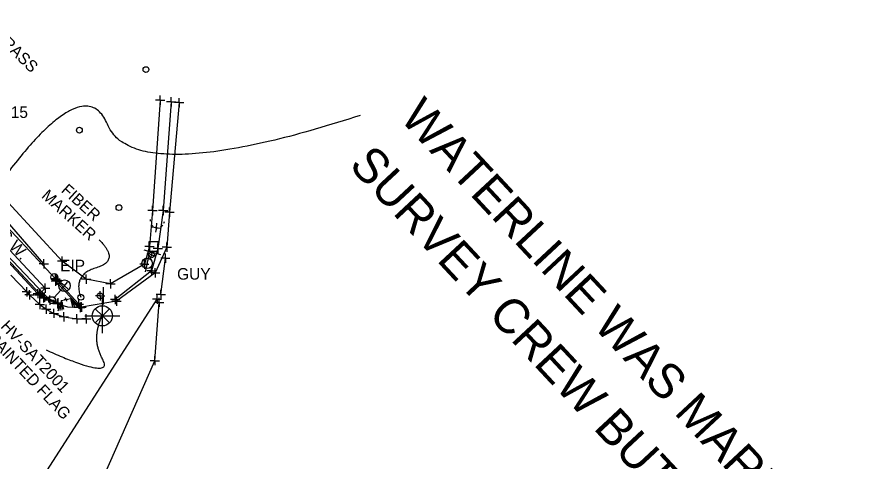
# Model space of a CAD drawing. Extents: x 0 to 1944463, y 0 to 420651.
# Drawn here: x 1943722 to 1944092.5, y 416896 to 417088.1 of the extents above; entities that cross this region are included whole.
import ezdxf

# ---------------------------------------------------------------- set-up
doc = ezdxf.new("R2010")
doc.units = 0
for name, color, linetype in [('AERIAL - CTRL - Points', 7, 'Continuous'), ('AERIAL - CTRL - Text', 7, 'Continuous'), ('SUR - CTRL - Points Text', 7, 'Continuous'), ('SUR - DTM - Breaklines', 7, 'Continuous'), ('SUR - DTM - Breaklines - Points - Locators', 7, 'Continuous'), ('SUR - DTM - Spot Points - Locators', 7, 'Continuous'), ('SUR - PROPERTY - Property Lines', 7, 'Continuous'), ('SUR - PROPERTY - Property Markers', 7, 'Continuous'), ('SUR - TR-CTRL - Signs and Devices', 7, 'Continuous'), ('SUR - TR-CTRL - Signs and Devices - Points - Locators', 7, 'Continuous'), ('SUR - TRAN - Features', 7, 'Continuous'), ('SUR - TRAN - Features - Points - Locators', 7, 'Continuous'), ('SUR - TRAN - Features Text', 7, 'Continuous'), ('SUR - TRAN - Roads', 7, 'Continuous'), ('SUR - UTL - Electric (Lighting)', 7, 'Continuous'), ('SUR - UTL - Electric (Lighting) - Points - Locators', 7, 'Continuous'), ('SUR - UTL - Fiber Optic Cable (Underground) Text', 7, 'Continuous'), ('SUR - UTL - Gas', 7, 'Continuous'), ('SUR - UTL - Gas - Points - Locators', 7, 'Continuous'), ('SUR - UTL - Poles and Miscellaneous', 7, 'Continuous'), ('SUR - UTL - Poles and Miscellaneous - Points - Locators', 7, 'Continuous'), ('SUR - UTL - Poles and Miscellaneous Text', 7, 'Continuous'), ('SUR - UTL - Water', 7, 'Continuous'), ('SUR - UTL - Water - Points - Locators', 7, 'Continuous'), ('SUR - UTL - Water Text', 7, 'Continuous'), ('SUR - VEG - Features Text', 7, 'Continuous')]:
    doc.layers.add(name, color=color, linetype=linetype)

msp = doc.modelspace()

# ---------------------------------------------------------------- linework, layer by layer
at = {"layer": 'AERIAL - CTRL - Points'}
for p, q in [((1943758.84, 416959.12), (1943758.84, 416966.62)), ((1943758.84, 416959.12), (1943755.78, 416962.19)), ((1943758.84, 416959.12), (1943761.91, 416962.19)), ((1943751.34, 416959.12), (1943758.84, 416959.12)), ((1943755.76, 416956.04), (1943758.84, 416959.12)), ((1943758.84, 416959.12), (1943758.84, 416959.12)), ((1943758.84, 416959.12), (1943766.34, 416959.12)), ((1943761.93, 416956.04), (1943758.84, 416959.12)), ((1943758.84, 416951.62), (1943758.84, 416959.12))]:
    msp.add_line(p, q, dxfattribs=at)
msp.add_circle((1943758.84, 416959.11), 4.35, dxfattribs=at)
at = {"layer": 'AERIAL - CTRL - Text'}
msp.add_open_spline([(1943734.51, 416944.38), (1943764.06, 416931.1), (1943753.96, 416949.44), (1943758.84, 416959.12)], degree=2, dxfattribs=at)
at = {"layer": 'SUR - DTM - Breaklines'}
for points in [[(1943783.81, 417052.2), (1943780.54, 417004.6), (1943779.21, 416989.03), (1943776.98, 416981.36), (1943762.37, 416972.89), (1943751.86, 416974.9), (1943741.51, 416982.77), (1943718.16, 417008.08), (1943685.34, 417042.9), (1943654.02, 417077.16), (1943664.76, 417124.78), (1943668.66, 417143.41)], [(1943733.58, 416981.53), (1943714.06, 417003.91), (1943681.39, 417038.59), (1943646.39, 417076.86)], [(1943792.05, 417051.17), (1943787.81, 417003.83), (1943786.74, 416988.77), (1943781.64, 416977.66), (1943764.93, 416965.46), (1943749.88, 416962.89)], [(1943788.57, 417051.56), (1943785.14, 417004.61), (1943782.85, 416988.15), (1943780.09, 416978.59), (1943764.41, 416966.11)], [(1943739.71, 416964.71), (1943733.87, 416967.21), (1943731.83, 416968.57), (1943702.93, 416999.44), (1943684.69, 417018.93), (1943683.82, 417020.85), (1943684.01, 417022.49), (1943684.83, 417023.71)], [(1943749.72, 416962.96), (1943748.68, 416964.11), (1943739.24, 416974.49)]]:
    msp.add_lwpolyline(points, dxfattribs=at)
at = {"layer": 'SUR - DTM - Breaklines - Points - Locators'}
for p, q in [((1943783.81, 417052.2), (1943783.81, 417054.2)), ((1943788.57, 417051.56), (1943788.57, 417053.56)), ((1943783.81, 417052.2), (1943781.81, 417052.2)), ((1943783.81, 417052.2), (1943785.81, 417052.2)), ((1943783.81, 417052.2), (1943783.81, 417050.2)), ((1943788.57, 417051.56), (1943786.57, 417051.56)), ((1943788.57, 417051.56), (1943790.57, 417051.56)), ((1943788.57, 417051.56), (1943788.57, 417049.56)), ((1943792.05, 417051.17), (1943790.05, 417051.17)), ((1943792.05, 417051.17), (1943792.05, 417053.17)), ((1943792.05, 417051.17), (1943794.05, 417051.17)), ((1943792.05, 417051.17), (1943792.05, 417049.17)), ((1943780.54, 417004.6), (1943780.54, 417006.6)), ((1943785.14, 417004.61), (1943785.14, 417006.61)), ((1943787.81, 417003.83), (1943787.81, 417005.83)), ((1943780.54, 417004.6), (1943778.54, 417004.6)), ((1943780.54, 417004.6), (1943782.54, 417004.6)), ((1943780.54, 417004.6), (1943780.54, 417002.6)), ((1943785.14, 417004.61), (1943783.14, 417004.61)), ((1943785.14, 417004.61), (1943787.14, 417004.61)), ((1943785.14, 417004.61), (1943785.14, 417002.61)), ((1943787.81, 417003.83), (1943785.81, 417003.83)), ((1943787.81, 417003.83), (1943789.81, 417003.83)), ((1943787.81, 417003.83), (1943787.81, 417001.83)), ((1943779.21, 416989.03), (1943779.21, 416991.03)), ((1943786.74, 416988.77), (1943786.74, 416990.77)), ((1943779.21, 416989.03), (1943777.21, 416989.03)), ((1943779.21, 416989.03), (1943781.21, 416989.03)), ((1943779.21, 416989.03), (1943779.21, 416987.03)), ((1943782.85, 416988.15), (1943780.85, 416988.15)), ((1943782.85, 416988.15), (1943782.85, 416990.15)), ((1943782.85, 416988.15), (1943784.85, 416988.15)), ((1943782.85, 416988.15), (1943782.85, 416986.15)), ((1943786.74, 416988.77), (1943784.74, 416988.77)), ((1943786.74, 416988.77), (1943788.74, 416988.77)), ((1943786.74, 416988.77), (1943786.74, 416986.77)), ((1943733.58, 416981.53), (1943733.58, 416983.53)), ((1943741.51, 416982.77), (1943741.51, 416984.77)), ((1943776.98, 416981.36), (1943776.98, 416983.36)), ((1943733.58, 416981.53), (1943731.58, 416981.53)), ((1943733.58, 416981.53), (1943735.58, 416981.53)), ((1943733.58, 416981.53), (1943733.58, 416979.53)), ((1943741.51, 416982.77), (1943739.51, 416982.77)), ((1943741.51, 416982.77), (1943743.51, 416982.77)), ((1943741.51, 416982.77), (1943741.51, 416980.77)), ((1943776.98, 416981.36), (1943774.98, 416981.36)), ((1943776.98, 416981.36), (1943778.98, 416981.36)), ((1943776.98, 416981.36), (1943776.98, 416979.36)), ((1943780.09, 416978.59), (1943780.09, 416980.59)), ((1943781.64, 416977.66), (1943781.64, 416979.66)), ((1943739.24, 416974.49), (1943739.24, 416976.49)), ((1943751.86, 416974.9), (1943751.86, 416976.9)), ((1943780.09, 416978.59), (1943778.09, 416978.59)), ((1943781.64, 416977.66), (1943779.64, 416977.66)), ((1943780.09, 416978.59), (1943782.09, 416978.59)), ((1943780.09, 416978.59), (1943780.09, 416976.59)), ((1943781.64, 416977.66), (1943783.64, 416977.66)), ((1943781.64, 416977.66), (1943781.64, 416975.66)), ((1943739.24, 416974.49), (1943737.24, 416974.49)), ((1943739.24, 416974.49), (1943741.24, 416974.49)), ((1943739.24, 416974.49), (1943739.24, 416972.49)), ((1943751.86, 416974.9), (1943749.86, 416974.9)), ((1943751.86, 416974.9), (1943753.86, 416974.9)), ((1943751.86, 416974.9), (1943751.86, 416972.9)), ((1943762.37, 416972.89), (1943760.37, 416972.89)), ((1943762.37, 416972.89), (1943762.37, 416974.89)), ((1943762.37, 416972.89), (1943764.37, 416972.89)), ((1943762.37, 416972.89), (1943762.37, 416970.89)), ((1943731.83, 416968.57), (1943729.83, 416968.57)), ((1943731.83, 416968.57), (1943731.83, 416970.57)), ((1943731.83, 416968.57), (1943733.83, 416968.57)), ((1943731.83, 416968.57), (1943731.83, 416966.57)), ((1943733.87, 416967.21), (1943733.87, 416969.21)), ((1943733.87, 416967.21), (1943731.87, 416967.21)), ((1943733.87, 416967.21), (1943735.87, 416967.21)), ((1943733.87, 416967.21), (1943733.87, 416965.21)), ((1943739.71, 416964.71), (1943737.71, 416964.71)), ((1943739.71, 416964.71), (1943739.71, 416966.71)), ((1943739.71, 416964.71), (1943741.71, 416964.71)), ((1943739.71, 416964.71), (1943739.71, 416962.71)), ((1943748.68, 416964.11), (1943748.68, 416966.11)), ((1943749.72, 416962.96), (1943749.72, 416964.96)), ((1943749.88, 416962.89), (1943749.88, 416964.89)), ((1943764.41, 416966.11), (1943762.41, 416966.11)), ((1943764.93, 416965.46), (1943762.93, 416965.46)), ((1943764.41, 416966.11), (1943764.41, 416968.11)), ((1943764.41, 416966.11), (1943766.41, 416966.11)), ((1943764.41, 416966.11), (1943764.41, 416964.11)), ((1943764.93, 416965.46), (1943764.93, 416967.46)), ((1943764.93, 416965.46), (1943766.93, 416965.46)), ((1943764.93, 416965.46), (1943764.93, 416963.46)), ((1943748.68, 416964.11), (1943746.68, 416964.11)), ((1943749.72, 416962.96), (1943747.72, 416962.96)), ((1943749.88, 416962.89), (1943747.88, 416962.89)), ((1943748.68, 416964.11), (1943750.68, 416964.11)), ((1943748.68, 416964.11), (1943748.68, 416962.11)), ((1943749.72, 416962.96), (1943751.72, 416962.96)), ((1943749.72, 416962.96), (1943749.72, 416960.96)), ((1943749.88, 416962.89), (1943751.88, 416962.89)), ((1943749.88, 416962.89), (1943749.88, 416960.89))]:
    msp.add_line(p, q, dxfattribs=at)
at = {"layer": 'SUR - DTM - Spot Points - Locators'}
for p, q in [((1943777.69, 417065.43), (1943777.69, 417065.43)), ((1943748.91, 417039.28), (1943748.91, 417039.28)), ((1943766.02, 417005.81), (1943766.02, 417005.81))]:
    msp.add_line(p, q, dxfattribs=at)
for centre in [(1943777.68, 417065.44), (1943748.9, 417039.29), (1943766.01, 417005.82)]:
    msp.add_circle(centre, 1.25, dxfattribs=at)
at = {"layer": 'SUR - PROPERTY - Property Lines'}
for p, q in [((1943726.16, 416969.43), (1943724.16, 416969.43)), ((1943726.16, 416969.43), (1943726.16, 416971.43)), ((1943726.16, 416969.43), (1943728.16, 416969.43)), ((1943726.16, 416969.43), (1943726.16, 416967.43)), ((1943727.36, 416968.16), (1943727.36, 416970.16)), ((1943727.36, 416968.16), (1943725.36, 416968.16)), ((1943727.36, 416968.16), (1943729.36, 416968.16)), ((1943727.36, 416968.16), (1943727.36, 416966.16)), ((1943731.81, 416963.96), (1943731.81, 416965.96)), ((1943731.81, 416963.96), (1943729.81, 416963.96)), ((1943731.81, 416963.96), (1943733.81, 416963.96)), ((1943731.81, 416963.96), (1943731.81, 416961.96)), ((1943734.56, 416961.94), (1943732.56, 416961.94)), ((1943734.56, 416961.94), (1943734.56, 416963.94)), ((1943734.56, 416961.94), (1943736.56, 416961.94)), ((1943734.56, 416961.94), (1943734.56, 416959.94)), ((1943737.91, 416960.18), (1943737.91, 416962.18)), ((1943737.91, 416960.18), (1943735.91, 416960.18)), ((1943737.91, 416960.18), (1943739.91, 416960.18)), ((1943737.91, 416960.18), (1943737.91, 416958.18)), ((1943742.17, 416958.72), (1943740.17, 416958.72)), ((1943742.17, 416958.72), (1943742.17, 416960.72)), ((1943742.17, 416958.72), (1943744.17, 416958.72)), ((1943742.17, 416958.72), (1943742.17, 416956.72)), ((1943747.76, 416957.86), (1943745.76, 416957.86)), ((1943747.76, 416957.86), (1943747.76, 416959.86)), ((1943747.76, 416957.86), (1943749.76, 416957.86)), ((1943747.76, 416957.86), (1943747.76, 416955.86)), ((1943751.91, 416957.83), (1943749.91, 416957.83)), ((1943751.91, 416957.83), (1943751.91, 416959.83)), ((1943751.91, 416957.83), (1943753.91, 416957.83)), ((1943751.91, 416957.83), (1943751.91, 416955.83))]:
    msp.add_line(p, q, dxfattribs=at)
at = {"layer": 'SUR - PROPERTY - Property Markers'}
msp.add_circle((1943738.1, 416975.85), 1.5, dxfattribs=at)
at = {"layer": 'SUR - TR-CTRL - Signs and Devices'}
for p, q in [((1943776.81, 416987.66), (1943784, 416985.54)), ((1943759.13, 416971.46), (1943759.13, 416963.96))]:
    msp.add_line(p, q, dxfattribs=at)
for centre in [(1943780.07, 416985.4), (1943757.88, 416967.69)]:
    msp.add_circle(centre, 1.25, dxfattribs=at)
at = {"layer": 'SUR - TR-CTRL - Signs and Devices - Points - Locators'}
for p, q in [((1943780.06, 416985.43), (1943780.63, 416987.35)), ((1943780.06, 416985.43), (1943778.14, 416985.99)), ((1943780.06, 416985.43), (1943779.49, 416983.51)), ((1943780.06, 416985.43), (1943781.98, 416984.86)), ((1943757.9, 416967.71), (1943757.9, 416969.71)), ((1943757.9, 416967.71), (1943755.9, 416967.71)), ((1943757.9, 416967.71), (1943757.9, 416965.71)), ((1943757.9, 416967.71), (1943759.9, 416967.71))]:
    msp.add_line(p, q, dxfattribs=at)
at = {"layer": 'SUR - TRAN - Features'}
for p, q in [((1943741.23, 416965.67), (1943739.59, 416961.13)), ((1943741.23, 416965.67), (1943740.47, 416961.35)), ((1943741.23, 416965.67), (1943745.11, 416966.65)), ((1943742.21, 416961.79), (1943741.23, 416965.67)), ((1943741.23, 416965.67), (1943741.34, 416961.57)), ((1943745.11, 416966.65), (1943746.09, 416962.77)), ((1943745.11, 416966.65), (1943748.71, 416963.43)), ((1943745.11, 416966.65), (1943747.83, 416963.21)), ((1943745.11, 416966.65), (1943746.96, 416962.99))]:
    msp.add_line(p, q, dxfattribs=at)
for points in [[(1943738.63, 416975.05), (1943710.04, 417005.57), (1943644.86, 417075.55)], [(1943739.52, 416964.25), (1943733.49, 416966.8), (1943731.67, 416968.06), (1943730.97, 416968.67), (1943702.44, 416999.08), (1943684.33, 417018.55), (1943683.3, 417020.99), (1943683.5, 417022.63), (1943684.23, 417023.84)], [(1943731.91, 416968.71), (1943734.2, 416971.01), (1943705.27, 417002.05), (1943685.05, 417023.73)], [(1943749.31, 416962.68), (1943738.67, 416974.07)], [(1943739.52, 416964.25), (1943743.73, 416962.97), (1943749.31, 416962.68)]]:
    msp.add_lwpolyline(points, dxfattribs=at)
at = {"layer": 'SUR - TRAN - Features - Points - Locators'}
for p, q in [((1943738.63, 416975.05), (1943738.63, 416977.05)), ((1943738.67, 416974.07), (1943738.67, 416976.07)), ((1943734.2, 416971.01), (1943734.2, 416973.01)), ((1943738.63, 416975.05), (1943736.63, 416975.05)), ((1943738.67, 416974.07), (1943736.67, 416974.07)), ((1943738.63, 416975.05), (1943740.63, 416975.05)), ((1943738.63, 416975.05), (1943738.63, 416973.05)), ((1943738.67, 416974.07), (1943740.67, 416974.07)), ((1943738.67, 416974.07), (1943738.67, 416972.07)), ((1943730.97, 416968.67), (1943728.97, 416968.67)), ((1943731.91, 416968.71), (1943729.91, 416968.71)), ((1943730.97, 416968.67), (1943730.97, 416970.67)), ((1943730.97, 416968.67), (1943732.97, 416968.67)), ((1943730.97, 416968.67), (1943730.97, 416966.67)), ((1943731.67, 416968.06), (1943731.67, 416970.06)), ((1943731.91, 416968.71), (1943731.91, 416970.71)), ((1943731.91, 416968.71), (1943733.91, 416968.71)), ((1943731.91, 416968.71), (1943731.91, 416966.71)), ((1943734.2, 416971.01), (1943732.2, 416971.01)), ((1943733.49, 416966.8), (1943733.49, 416968.8)), ((1943734.2, 416971.01), (1943736.2, 416971.01)), ((1943734.2, 416971.01), (1943734.2, 416969.01)), ((1943731.67, 416968.06), (1943729.67, 416968.06)), ((1943733.49, 416966.8), (1943731.49, 416966.8)), ((1943731.67, 416968.06), (1943733.67, 416968.06)), ((1943731.67, 416968.06), (1943731.67, 416966.06)), ((1943733.49, 416966.8), (1943735.49, 416966.8)), ((1943733.49, 416966.8), (1943733.49, 416964.8)), ((1943739.52, 416964.25), (1943739.52, 416966.25)), ((1943743.17, 416966.16), (1943742.39, 416965.96)), ((1943743.17, 416966.16), (1943742.97, 416966.94)), ((1943743.17, 416966.16), (1943743.95, 416966.36)), ((1943743.17, 416966.16), (1943743.37, 416965.38)), ((1943749.31, 416962.68), (1943749.31, 416964.68)), ((1943739.52, 416964.25), (1943737.52, 416964.25)), ((1943739.52, 416964.25), (1943741.52, 416964.25)), ((1943739.52, 416964.25), (1943739.52, 416962.25)), ((1943749.31, 416962.68), (1943747.31, 416962.68)), ((1943749.31, 416962.68), (1943751.31, 416962.68)), ((1943749.31, 416962.68), (1943749.31, 416960.68))]:
    msp.add_line(p, q, dxfattribs=at)
at = {"layer": 'SUR - TRAN - Roads'}
msp.add_lwpolyline([(1943719.28, 416976.69), (1943726.16, 416969.43), (1943727.36, 416968.16), (1943731.81, 416963.96), (1943734.56, 416961.94), (1943737.91, 416960.18), (1943742.17, 416958.72), (1943747.76, 416957.86), (1943751.91, 416957.83)], dxfattribs=at)
at = {"layer": 'SUR - UTL - Electric (Lighting)'}
msp.add_line((1943738.06, 416967), (1943740.84, 416970.21), dxfattribs=at)
for centre, radius in [((1943742.48, 416972.1), 2.5), ((1943737.08, 416965.86), 1.5)]:
    msp.add_circle(centre, radius, dxfattribs=at)
at = {"layer": 'SUR - UTL - Electric (Lighting) - Points - Locators'}
for q in [(1943740.97, 416973.39), (1943741.18, 416970.57), (1943743.8, 416973.59), (1943744, 416970.77)]:
    msp.add_line((1943742.49, 416972.08), q, dxfattribs=at)
at = {"layer": 'SUR - UTL - Fiber Optic Cable (Underground) Text'}
msp.add_open_spline([(1943757.4, 416991.99), (1943766.62, 416982.9), (1943745.92, 416976.84), (1943749.55, 416967.1)], degree=2, dxfattribs=at)
at = {"layer": 'SUR - UTL - Gas'}
msp.add_line((1943780.95, 416989.01), (1943780.95, 416989.01), dxfattribs=at)
for points in [[(1943778.95, 416991.01), (1943778.95, 416987.01), (1943782.95, 416987.01), (1943782.95, 416991.01), (1943778.95, 416991.01)], [(1943784.08, 416968.29), (1943786.06, 416983.99)], [(1943659.63, 416706.42), (1943699.05, 416836.64), (1943782.46, 416966.29)], [(1943749.68, 416699.6), (1943706.85, 416732.94), (1943730.4, 416823.99), (1943781.49, 416939.73), (1943783.33, 416964.93)]]:
    msp.add_lwpolyline(points, dxfattribs=at)
at = {"layer": 'SUR - UTL - Gas - Points - Locators'}
for p, q in [((1943786.06, 416983.99), (1943784.06, 416983.99)), ((1943786.06, 416983.99), (1943786.06, 416985.99)), ((1943786.06, 416983.99), (1943788.06, 416983.99)), ((1943786.06, 416983.99), (1943786.06, 416981.99)), ((1943784.08, 416968.29), (1943782.08, 416968.29)), ((1943782.46, 416966.29), (1943782.46, 416968.29)), ((1943784.08, 416968.29), (1943784.08, 416970.29)), ((1943784.08, 416968.29), (1943786.08, 416968.29)), ((1943784.08, 416968.29), (1943784.08, 416966.29)), ((1943782.46, 416966.29), (1943780.46, 416966.29)), ((1943783.33, 416964.93), (1943781.33, 416964.93)), ((1943782.46, 416966.29), (1943784.46, 416966.29)), ((1943782.46, 416966.29), (1943782.46, 416964.29)), ((1943783.33, 416964.93), (1943783.33, 416966.93)), ((1943783.33, 416964.93), (1943785.33, 416964.93)), ((1943783.33, 416964.93), (1943783.33, 416962.93)), ((1943781.49, 416939.73), (1943779.49, 416939.73)), ((1943781.49, 416939.73), (1943781.49, 416941.73)), ((1943781.49, 416939.73), (1943783.49, 416939.73)), ((1943781.49, 416939.73), (1943781.49, 416937.73))]:
    msp.add_line(p, q, dxfattribs=at)
at = {"layer": 'SUR - UTL - Poles and Miscellaneous'}
for p, q in [((1943782.06, 416996.48), (1943782.16, 416997.17)), ((1943778.21, 416981.78), (1943779.15, 416985.41)), ((1943778.21, 416981.78), (1943777.28, 416978.15)), ((1943749.55, 416967.1), (1943749.55, 416967.1))]:
    msp.add_line(p, q, dxfattribs=at)
for centre, radius in [((1943778.21, 416981.78), 2.25), ((1943749.54, 416967.11), 1.25)]:
    msp.add_circle(centre, radius, dxfattribs=at)
for start, end in [(171.8731, 186.4939), (213.7509, 234.0934), (295.4358, 320.2058), (337.0596, 350.949), (249.394, 275.9093)]:
    msp.add_arc((1943782.57, 417000.27), 3.12, start, end, dxfattribs=at)
at = {"layer": 'SUR - UTL - Poles and Miscellaneous - Points - Locators'}
for q in [(1943782.44, 416999.15), (1943780.18, 416997.45), (1943781.87, 416995.19), (1943784.14, 416996.89)]:
    msp.add_line((1943782.16, 416997.17), q, dxfattribs=at)
at = {"layer": 'SUR - UTL - Water'}
msp.add_lwpolyline([(1943736.14, 416965.92), (1943698.62, 417005.31), (1943662.81, 417044.53), (1943623.49, 417086.6), (1943587.47, 417125.24), (1943551.37, 417163.71), (1943514.78, 417202.79), (1943477.5, 417242.51), (1943442.36, 417279.47), (1943414.8, 417309.89), (1943402.76, 417322.35)], dxfattribs=at)
at = {"layer": 'SUR - UTL - Water - Points - Locators'}
for q in [(1943734.14, 416965.92), (1943736.14, 416967.92), (1943738.14, 416965.92), (1943736.14, 416963.92)]:
    msp.add_line((1943736.14, 416965.92), q, dxfattribs=at)
at = {"layer": 'SUR - UTL - Water Text'}
msp.add_open_spline([(1943870.25, 417045.63), (1943772.69, 417014.05), (1943749.45, 417069.46), (1943703.36, 417000.31)], degree=2, dxfattribs=at)

# ---------------------------------------------------------------- texts
at = {"layer": 'AERIAL - CTRL - Text'}
for s, p in [('HV-SAT2001', (1943714.59, 416954.26)), ('PAINTED FLAG', (1943709.1, 416949.15))]:
    msp.add_text(s, height=5, rotation=313, dxfattribs=at).set_placement(p)
at = {"layer": 'SUR - CTRL - Points Text'}
msp.add_text('GPS 16-02-15', height=5, dxfattribs=at).set_placement((1943683.97, 417044.56))
at = {"layer": 'SUR - PROPERTY - Property Markers'}
msp.add_text('EIP', height=5, dxfattribs=at).set_placement((1943740.6, 416978.34))
at = {"layer": 'SUR - TRAN - Features Text'}
msp.add_text('S.W.', height=5, rotation=312.9833, dxfattribs=at).set_placement((1943713.98, 416993.46))
at = {"layer": 'SUR - UTL - Fiber Optic Cable (Underground) Text'}
for s, p in [('MARKER', (1943732.21, 417010.45)), ('FIBER', (1943740.7, 417012.86))]:
    msp.add_text(s, height=5, rotation=317.7091, dxfattribs=at).set_placement(p)
at = {"layer": 'SUR - UTL - Poles and Miscellaneous Text'}
msp.add_text('GUY', height=5, dxfattribs=at).set_placement((1943791.13, 416974.72))
at = {"layer": 'SUR - UTL - Water Text'}
for s, p in [('WATERLINE WAS MARKED BY UTILITY OWNER AND LOCATED IN THE FIELD BY TDOT', (1943886.85, 417044.23)), ("SURVEY CREW BUT UTILITY OWNER IS SAYING WATERLINE DOESN'T EXIST.", (1943864.91, 417023.77))]:
    msp.add_text(s, height=15, rotation=313, dxfattribs=at).set_placement(p)
at = {"layer": 'SUR - VEG - Features Text'}
msp.add_text('GRASS', height=5, rotation=315.4809, dxfattribs=at).set_placement((1943711.36, 417080.19))

doc.saveas('drawing.dxf')
